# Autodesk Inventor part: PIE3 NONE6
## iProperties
Shininess: 64.0
Length Units: 11269
Angle Units: 11279
Time Units: 11290
Mass Units: 11286
Length Display Precision: 3
Angle Display Precision: 2
Compacted: True
Part Number: PIE3 NONE6
Document SubType Name: Modeling
Created: 2004-08
Designer: John Blackburn
Manufacturer: Standard
Standards Organization: Custom
Density: 0.0
Volumn: 0.0
Area: 0.0
PropertySet Name: Model Information
Control State: 0
Master: False
Checked Out: False
Author: John Blackburn
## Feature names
1. Erst1
